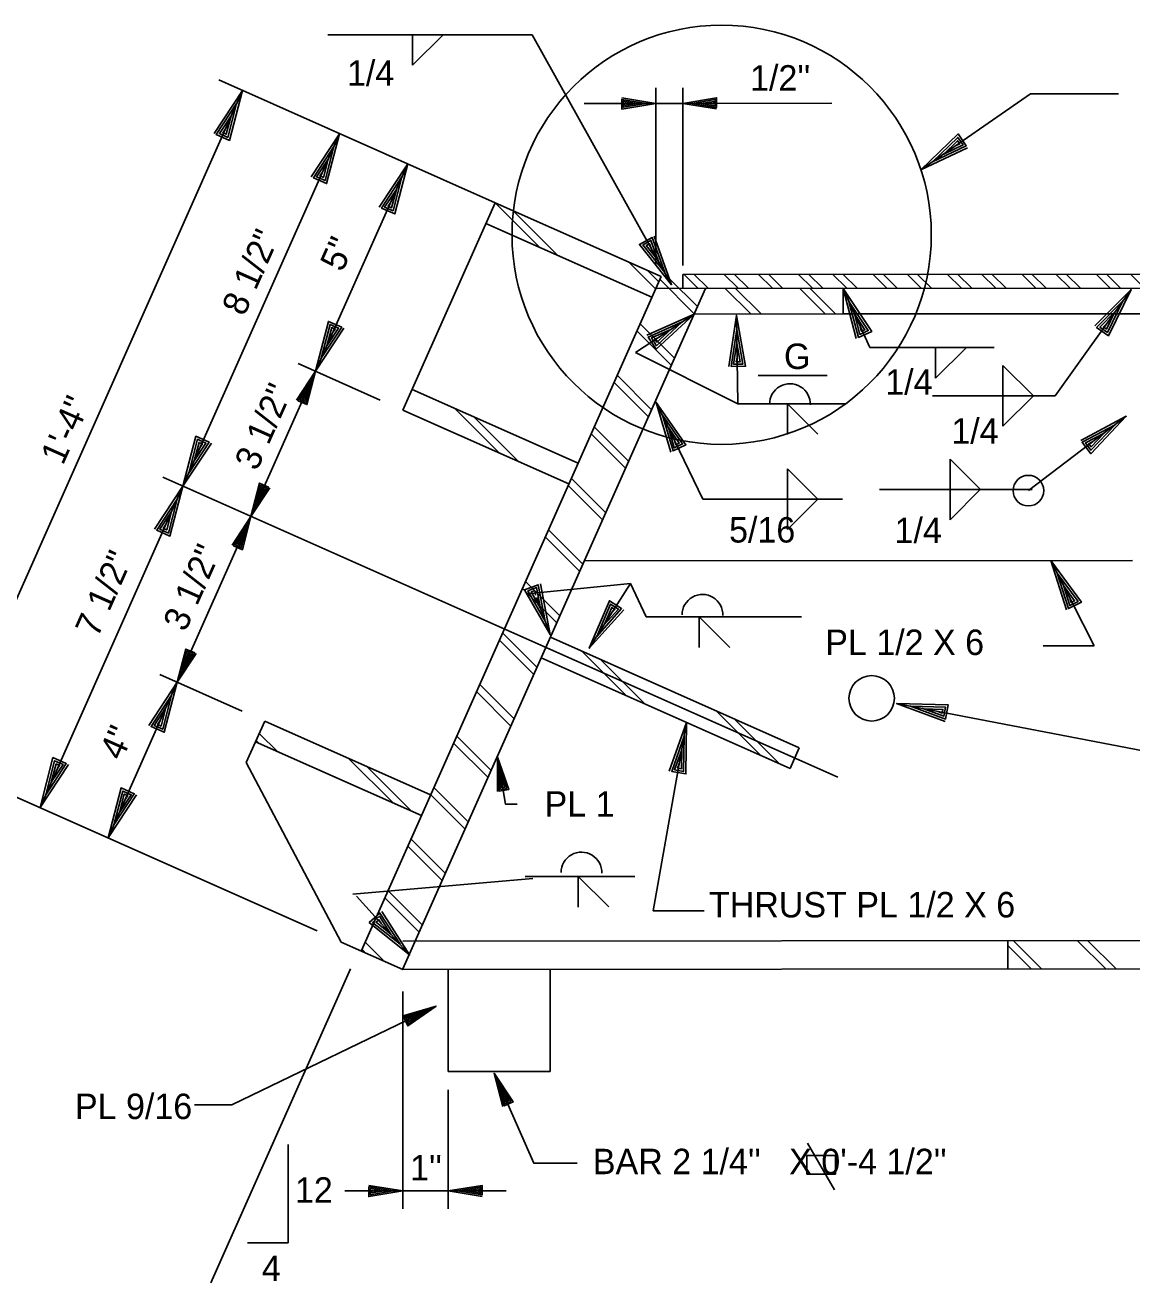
# Model space of a CAD drawing. Extents: x 0.1 to 13.5, y 0.1 to 9.5.
# Drawn here: x 1.182 to 3.214, y 3.086 to 5.396 of the extents above; entities that cross this region are included whole.
import ezdxf

# ---------------------------------------------------------------- set-up
doc = ezdxf.new("R2010")
doc.units = 0
for name, color, linetype in [('Level 1', 7, 'Continuous'), ('Level 25', 7, 'Continuous'), ('Level 3', 7, 'Continuous'), ('Level 44', 7, 'Continuous'), ('Level 50', 7, 'Continuous')]:
    doc.layers.add(name, color=color, linetype=linetype)

msp = doc.modelspace()

# ---------------------------------------------------------------- linework, layer by layer
at = {"layer": 'Level 1'}
for p, q in [((3.0509, 4.2563), (3.1448, 4.2563)), ((2.335, 3.7695), (2.4289, 3.7695)), ((1.7687, 3.255), (1.8752, 3.255)), ((1.8752, 3.255), (1.9586, 3.255)), ((1.9586, 3.255), (2.0649, 3.255)), ((1.5901, 3.1597), (1.6649, 3.1597))]:
    msp.add_line(p, q, dxfattribs=at)
at = {"layer": 'Level 25'}
for p, q in [((2.113, 5.3781), (1.7379, 5.3781)), ((1.8933, 5.3787), (1.8933, 5.3224)), ((1.8933, 5.3224), (1.9492, 5.3783)), ((2.113, 5.3781), (2.3689, 4.9191)), ((1.5374, 5.2951), (2.0449, 5.0696)), ((1.0308, 4.0382), (1.5809, 5.2758)), ((2.3397, 4.9544), (2.3397, 5.281)), ((2.3893, 4.9544), (2.3893, 5.281)), ((2.3397, 5.2522), (2.2081, 5.2521)), ((2.3397, 5.2522), (2.3397, 5.2522)), ((2.3893, 5.2522), (2.3397, 5.2522)), ((2.6633, 5.2524), (2.3893, 5.2522)), ((2.3893, 5.2522), (2.3893, 5.2522)), ((1.4716, 4.5493), (1.7593, 5.1965)), ((1.7151, 4.7602), (1.8843, 5.1409)), ((1.8757, 4.6888), (2.0449, 5.0696)), ((2.0449, 5.0696), (2.3495, 4.9342)), ((2.3326, 4.8961), (2.028, 5.0315)), ((1.7995, 3.6966), (2.3495, 4.9342)), ((2.3563, 4.9418), (2.3563, 4.9418)), ((4.3479, 4.9394), (2.3893, 4.9382)), ((2.3893, 4.9119), (2.3893, 4.938)), ((1.8757, 3.6628), (2.4309, 4.9122)), ((4.3479, 4.9133), (2.3397, 4.9121)), ((2.3689, 4.9191), (2.3689, 4.9191)), ((2.6838, 4.8654), (2.6838, 4.9123)), ((2.7327, 4.8036), (2.6838, 4.9123)), ((2.6838, 4.9123), (2.6838, 4.9123)), ((3.0732, 4.7152), (3.2126, 4.9106)), ((3.2126, 4.9106), (3.2126, 4.9106)), ((2.6944, 4.8886), (2.6944, 4.8886)), ((3.1975, 4.8894), (3.1975, 4.8894)), ((2.3027, 4.7944), (2.4101, 4.8653)), ((2.3884, 4.8509), (2.3884, 4.8509)), ((2.6838, 4.8654), (2.4101, 4.8653)), ((2.4101, 4.8653), (2.4101, 4.8653)), ((2.4903, 4.7006), (2.488, 4.8628)), ((2.488, 4.8628), (2.488, 4.8628)), ((4.3479, 4.8664), (2.6838, 4.8654)), ((2.4884, 4.8368), (2.4884, 4.8368)), ((2.4903, 4.7006), (2.3027, 4.7944)), ((2.7327, 4.8036), (2.9611, 4.8036)), ((2.8537, 4.8036), (2.8537, 4.7473)), ((2.8537, 4.7473), (2.9096, 4.8032)), ((1.5966, 4.4937), (1.7151, 4.7602)), ((1.6833, 4.7743), (1.8339, 4.7074)), ((1.7151, 4.7602), (1.7151, 4.7602)), ((2.9773, 4.7708), (3.0332, 4.715)), ((2.9773, 4.7146), (2.9773, 4.7708)), ((2.6546, 4.7524), (2.5277, 4.7524)), ((2.1972, 4.5915), (1.8926, 4.7269)), ((3.0732, 4.7152), (2.8478, 4.7152)), ((3.0732, 4.7152), (2.9269, 4.7152)), ((2.9773, 4.7158), (2.9773, 4.6595)), ((2.9773, 4.6595), (3.0332, 4.7154)), ((2.1803, 4.5534), (1.8757, 4.6888)), ((1.8757, 4.6888), (1.8757, 4.6888)), ((2.4263, 4.5254), (2.3408, 4.7029)), ((2.3408, 4.7029), (2.3408, 4.7029)), ((2.4903, 4.7006), (2.6888, 4.7006)), ((2.5818, 4.7006), (2.5818, 4.6443)), ((2.5818, 4.7006), (2.6377, 4.6446)), ((2.3521, 4.6794), (2.3521, 4.6794)), ((3.024, 4.541), (3.2038, 4.6777)), ((3.2038, 4.6777), (3.2038, 4.6777)), ((3.1831, 4.6619), (3.1831, 4.6619)), ((2.8802, 4.5991), (2.9361, 4.5432)), ((2.8802, 4.5428), (2.8802, 4.5991)), ((2.5817, 4.5811), (2.6376, 4.5252)), ((2.5817, 4.5248), (2.5817, 4.5811)), ((2.6744, 4.0147), (1.4348, 4.5656)), ((1.2092, 3.9589), (1.4716, 4.5492)), ((3.0312, 4.5434), (2.7507, 4.5434)), ((3.0312, 4.5434), (2.8298, 4.5434)), ((2.8802, 4.544), (2.8802, 4.4877)), ((2.8802, 4.4877), (2.9361, 4.5436)), ((2.6824, 4.5254), (2.4263, 4.5254)), ((2.6824, 4.5254), (2.4263, 4.5254)), ((2.5817, 4.526), (2.5817, 4.4698)), ((2.5817, 4.4698), (2.6376, 4.5256)), ((1.4613, 4.1891), (1.5966, 4.4937)), ((1.5966, 4.4937), (1.5966, 4.4937)), ((3.2154, 4.4126), (2.2087, 4.412)), ((2.2932, 4.3702), (2.1098, 4.3522)), ((2.2932, 4.3702), (2.2177, 4.2515)), ((2.322, 4.309), (2.2932, 4.3702)), ((2.1206, 4.345), (2.1458, 4.2767)), ((2.1368, 4.3011), (2.1368, 4.3011)), ((2.322, 4.309), (2.6072, 4.309)), ((2.4196, 4.309), (2.4196, 4.2528)), ((2.4196, 4.309), (2.4756, 4.2531)), ((2.1458, 4.2767), (2.1458, 4.2767)), ((2.2317, 4.2734), (2.2317, 4.2734)), ((2.6034, 4.069), (2.1465, 4.2721)), ((2.2177, 4.2515), (2.2177, 4.2515)), ((2.5865, 4.031), (2.1296, 4.234)), ((1.3343, 3.9034), (1.4613, 4.1891)), ((1.4295, 4.2032), (1.5801, 4.1363)), ((1.588, 4.0415), (1.6219, 4.1177)), ((1.9265, 3.9823), (1.6219, 4.1177)), ((1.6219, 4.1177), (1.6219, 4.1177)), ((0.955, 4.0719), (1.7181, 3.7328)), ((1.9096, 3.9442), (1.6049, 4.0796)), ((1.6049, 4.0796), (1.6049, 4.0796)), ((2.5865, 4.031), (2.6034, 4.069)), ((2.1142, 3.8288), (1.7834, 3.8)), ((2.0998, 3.8324), (2.3012, 3.8324)), ((2.1974, 3.8324), (2.1974, 3.7762)), ((2.1974, 3.8324), (2.2534, 3.7765)), ((1.7906, 3.7964), (1.8877, 3.6885)), ((1.8752, 3.6618), (1.7622, 3.7121)), ((1.8703, 3.7079), (1.8703, 3.7079)), ((4.3486, 3.7154), (1.8752, 3.7139)), ((2.9862, 3.6625), (2.9862, 3.7146)), ((1.8877, 3.6885), (1.8877, 3.6885)), ((1.523, 3.0863), (1.7793, 3.663)), ((4.3486, 3.6633), (1.8752, 3.6618)), ((1.9586, 3.4744), (1.9586, 3.6617)), ((2.1461, 3.4744), (2.1461, 3.6617)), ((1.8752, 3.2219), (1.8752, 3.6213)), ((2.1461, 3.4745), (1.9586, 3.4744)), ((1.9586, 3.2219), (1.9586, 3.4404)), ((1.6649, 3.1597), (1.6649, 3.3406)), ((2.6681, 3.2568), (2.6183, 3.3429)), ((2.6698, 3.3203), (2.6175, 3.3203)), ((2.6175, 3.2861), (2.6175, 3.3203)), ((2.6698, 3.2861), (2.6698, 3.3203)), ((2.6698, 3.2861), (2.6175, 3.2861))]:
    msp.add_line(p, q, dxfattribs=at)
for points in [[(2.3369, 5.0083), (2.3689, 4.9191), (2.3098, 4.9932), (2.333, 5.0061), (2.3563, 4.9418), (2.3162, 4.9921), (2.331, 5.0004), (2.3441, 4.9636), (2.3225, 4.9911), (2.3286, 4.9945), (2.3314, 4.9863)], [(2.708, 4.8207), (2.6838, 4.9123), (2.7363, 4.8334), (2.7121, 4.8225), (2.6944, 4.8886), (2.7301, 4.835), (2.7146, 4.828), (2.7047, 4.8658), (2.7239, 4.8366), (2.7175, 4.8337), (2.7154, 4.8421)], [(3.1457, 4.8435), (3.2126, 4.9106), (3.1709, 4.8255), (3.1493, 4.8409), (3.1975, 4.8894), (3.1692, 4.8316), (3.1553, 4.8415), (3.183, 4.8691), (3.1674, 4.8378), (3.1617, 4.8418), (3.1679, 4.8479)], [(2.3235, 4.8267), (2.4101, 4.8653), (2.3406, 4.8008), (2.326, 4.8229), (2.3884, 4.8509), (2.3412, 4.8072), (2.3318, 4.8214), (2.3675, 4.8372), (2.3418, 4.8136), (2.3379, 4.8194), (2.3458, 4.8228)], [(2.4738, 4.7691), (2.488, 4.8628), (2.5048, 4.7695), (2.4783, 4.7691), (2.4884, 4.8368), (2.4998, 4.7734), (2.4828, 4.7732), (2.4887, 4.8118), (2.4947, 4.7774), (2.4877, 4.7773), (2.4891, 4.7858)], [(2.3674, 4.6119), (2.3408, 4.7029), (2.3953, 4.6254), (2.3715, 4.6139), (2.3521, 4.6794), (2.3891, 4.6268), (2.3738, 4.6194), (2.3629, 4.6569), (2.3828, 4.6282), (2.3765, 4.6252), (2.3742, 4.6335)], [(3.12, 4.6334), (3.2038, 4.6777), (3.1388, 4.6088), (3.1227, 4.6299), (3.1831, 4.6619), (3.1389, 4.6152), (3.1286, 4.6287), (3.1632, 4.6468), (3.1391, 4.6216), (3.1348, 4.6271), (3.1425, 4.6311)], [(2.128, 4.3698), (2.1458, 4.2767), (2.0989, 4.359), (2.1238, 4.3682), (2.1368, 4.3011), (2.105, 4.357), (2.121, 4.3629), (2.1282, 4.3245), (2.1111, 4.355), (2.1177, 4.3574), (2.1192, 4.3489)], [(2.281, 4.3221), (2.2177, 4.2515), (2.2548, 4.3387), (2.2772, 4.3245), (2.2317, 4.2734), (2.2569, 4.3326), (2.2713, 4.3235), (2.2451, 4.2945), (2.259, 4.3266), (2.2649, 4.3228), (2.2591, 4.3164)], [(1.8367, 3.7684), (1.8877, 3.6885), (1.8136, 3.7477), (1.8333, 3.7654), (1.8703, 3.7079), (1.82, 3.7481), (1.8326, 3.7594), (1.8536, 3.7265), (1.8264, 3.7484), (1.8316, 3.7531), (1.8362, 3.7458)]]:
    msp.add_lwpolyline(points, dxfattribs=at)
for centre, radius in [((2.4608, 5.0109), 0.3849), ((3.024, 4.541), 0.0281), ((2.7363, 4.1597), 0.0417)]:
    msp.add_circle(centre, radius, dxfattribs=at)
for centre in [(2.5862, 4.6998), (2.4256, 4.3129), (2.2034, 3.8396)]:
    msp.add_arc(centre, 0.0375, 358.4208, 180, dxfattribs=at)
at = {"layer": 'Level 3'}
for p, q in [((2.0495, 4.0518), (2.0495, 4.0518)), ((2.0523, 4.0347), (2.0523, 4.0347)), ((1.9209, 3.5869), (1.9209, 3.5869)), ((1.9365, 3.5944), (1.9365, 3.5944)), ((2.0431, 3.4713), (2.0431, 3.4713)), ((2.0501, 3.4554), (2.0501, 3.4554))]:
    msp.add_line(p, q, dxfattribs=at)
for points in [[(2.0854, 3.9655), (2.0639, 3.9655), (2.0495, 4.0518)], [(2.0495, 3.9886), (2.0495, 4.0518), (2.0699, 3.992), (2.0525, 3.9891), (2.0523, 4.0347), (2.0662, 3.9941), (2.055, 3.9923), (2.0551, 4.0183), (2.0625, 3.9962), (2.0579, 3.9954), (2.0579, 4.0012)], [(1.493, 3.4134), (1.5614, 3.4134), (1.9365, 3.5944)], [(1.8759, 3.5766), (1.9365, 3.5944), (1.8848, 3.558), (1.8772, 3.5739), (1.9209, 3.5869), (1.8858, 3.5622), (1.8809, 3.5724), (1.9059, 3.5796), (1.8868, 3.5663), (1.8847, 3.5705), (1.8903, 3.5721)], [(2.1954, 3.3058), (2.1159, 3.3058), (2.0431, 3.4713)], [(2.0588, 3.4101), (2.0431, 3.4713), (2.0777, 3.4184), (2.0615, 3.4113), (2.0501, 3.4554), (2.0736, 3.4195), (2.0632, 3.4149), (2.0568, 3.4402), (2.0694, 3.4206), (2.0652, 3.4187), (2.0638, 3.4243)]]:
    msp.add_lwpolyline(points, dxfattribs=at)
at = {"layer": 'Level 44'}
for p, q in [((3.0279, 5.2697), (2.8268, 5.1301)), ((3.0279, 5.2697), (3.1892, 5.2697)), ((2.1269, 4.9875), (2.0449, 5.0695)), ((2.1609, 4.9724), (2.0788, 5.0545)), ((2.3395, 4.9116), (2.2909, 4.9602)), ((2.3453, 4.9247), (2.3249, 4.9451)), ((2.4104, 4.866), (2.3473, 4.9291)), ((2.4162, 4.879), (2.3653, 4.9299)), ((2.4166, 4.9133), (2.3917, 4.9382)), ((2.4354, 4.9133), (2.4106, 4.9382)), ((2.4903, 4.9133), (2.4654, 4.9382)), ((2.5092, 4.9133), (2.4843, 4.9382)), ((2.5533, 4.9133), (2.5284, 4.9382)), ((2.5722, 4.9133), (2.5473, 4.9382)), ((2.627, 4.9133), (2.6021, 4.9382)), ((2.6459, 4.9133), (2.621, 4.9382)), ((2.69, 4.9133), (2.6651, 4.9382)), ((2.7089, 4.9133), (2.684, 4.9382)), ((2.7637, 4.9133), (2.7388, 4.9382)), ((2.7826, 4.9133), (2.7577, 4.9382)), ((2.8267, 4.9133), (2.8018, 4.9382)), ((2.8456, 4.9133), (2.8207, 4.9382)), ((2.9004, 4.9133), (2.8755, 4.9382)), ((2.9193, 4.9133), (2.8944, 4.9382)), ((2.9634, 4.9133), (2.9386, 4.9382)), ((2.9823, 4.9133), (2.9574, 4.9382)), ((3.0371, 4.9133), (3.0123, 4.9382)), ((3.056, 4.9133), (3.0311, 4.9382)), ((3.1001, 4.9133), (3.0753, 4.9382)), ((3.119, 4.9133), (3.0941, 4.9382)), ((3.1738, 4.9133), (3.149, 4.9382)), ((3.1927, 4.9133), (3.1678, 4.9382)), ((3.2368, 4.9133), (3.212, 4.9382)), ((2.5143, 4.8654), (2.4675, 4.9122)), ((2.5331, 4.8654), (2.4864, 4.9122)), ((2.651, 4.8654), (2.6042, 4.9122)), ((2.6698, 4.8654), (2.6231, 4.9122)), ((2.3684, 4.7713), (2.3052, 4.8344)), ((2.3742, 4.7844), (2.311, 4.8475)), ((2.3263, 4.6767), (2.2632, 4.7398)), ((2.3321, 4.6897), (2.269, 4.7529)), ((2.0531, 4.61), (1.9711, 4.692)), ((2.0871, 4.5949), (2.005, 4.6769)), ((2.2842, 4.582), (2.2211, 4.6452)), ((2.29, 4.5951), (2.2269, 4.6582)), ((2.2422, 4.4874), (2.179, 4.5505)), ((2.248, 4.5004), (2.1848, 4.5636)), ((2.2059, 4.4058), (2.1428, 4.4689)), ((2.2001, 4.3927), (2.137, 4.4559)), ((3.1448, 4.2563), (3.0651, 4.4125)), ((2.1638, 4.3112), (2.1007, 4.3743)), ((2.158, 4.2981), (2.0949, 4.3612)), ((2.1218, 4.2165), (2.0586, 4.2796)), ((2.116, 4.2035), (2.0528, 4.2666)), ((2.2861, 4.1644), (2.204, 4.2465)), ((2.32, 4.1494), (2.2379, 4.2315)), ((2.0797, 4.1219), (2.0166, 4.185)), ((2.0739, 4.1088), (2.0108, 4.1719)), ((2.5322, 4.0551), (2.4501, 4.1372)), ((3.5935, 3.9938), (2.782, 4.1501)), ((2.335, 3.7695), (2.3963, 4.1155)), ((2.5661, 4.04), (2.484, 4.1221)), ((1.6459, 4.0614), (1.6119, 4.0953)), ((2.0376, 4.0272), (1.9745, 4.0904)), ((1.6119, 4.0765), (1.6061, 4.0823)), ((2.0318, 4.0142), (1.9687, 4.0773)), ((1.858, 3.9671), (1.7759, 4.0492)), ((1.7622, 3.7121), (1.588, 4.0415)), ((1.8919, 3.952), (1.8099, 4.0341)), ((1.9956, 3.9326), (1.9324, 3.9957)), ((1.9898, 3.9195), (1.9266, 3.9827)), ((1.9477, 3.8249), (1.8846, 3.888)), ((1.9535, 3.8379), (1.8904, 3.9011)), ((1.9056, 3.7302), (1.8425, 3.7934)), ((1.9114, 3.7433), (1.8483, 3.8064)), ((1.805, 3.6941), (1.8005, 3.6987)), ((1.839, 3.6791), (1.8063, 3.7118)), ((3.0293, 3.6628), (2.9862, 3.7059)), ((3.0482, 3.6628), (2.9964, 3.7146)), ((3.166, 3.6628), (3.1143, 3.7146)), ((3.1849, 3.6628), (3.1331, 3.7146))]:
    msp.add_line(p, q, dxfattribs=at)
at = {"layer": 'Level 50'}
for p, q in [((1.5809, 5.2758), (1.5809, 5.2758)), ((1.5703, 5.252), (1.5703, 5.252)), ((2.3224, 5.2522), (2.3224, 5.2522)), ((2.3397, 5.2522), (2.3397, 5.2522)), ((2.3893, 5.2522), (2.3893, 5.2522)), ((2.4066, 5.2522), (2.4066, 5.2522)), ((1.7593, 5.1965), (1.7593, 5.1965)), ((1.7487, 5.1727), (1.7487, 5.1727)), ((1.8843, 5.1409), (1.8843, 5.1409)), ((2.8268, 5.1301), (2.8268, 5.1301)), ((2.8482, 5.1449), (2.8482, 5.1449)), ((1.8738, 5.1172), (1.8738, 5.1172)), ((1.7257, 4.784), (1.7257, 4.784)), ((1.7151, 4.7602), (1.7151, 4.7602)), ((1.7151, 4.7602), (1.7151, 4.7602)), ((1.7081, 4.7444), (1.7081, 4.7444)), ((1.4822, 4.573), (1.4822, 4.573)), ((1.4716, 4.5493), (1.4716, 4.5493)), ((1.4716, 4.5492), (1.4716, 4.5492)), ((1.4611, 4.5255), (1.4611, 4.5255)), ((1.6037, 4.5095), (1.6037, 4.5095)), ((1.5966, 4.4937), (1.5966, 4.4937)), ((1.5966, 4.4937), (1.5966, 4.4937)), ((1.5896, 4.4778), (1.5896, 4.4778)), ((3.0651, 4.4125), (3.0651, 4.4125)), ((3.0769, 4.3894), (3.0769, 4.3894)), ((1.4683, 4.2049), (1.4683, 4.2049)), ((1.4613, 4.1891), (1.4613, 4.1891)), ((1.4613, 4.1891), (1.4613, 4.1891)), ((1.4507, 4.1653), (1.4507, 4.1653)), ((2.782, 4.1501), (2.782, 4.1501)), ((2.8076, 4.1451), (2.8076, 4.1451)), ((2.3963, 4.1155), (2.3963, 4.1155)), ((2.3917, 4.0899), (2.3917, 4.0899)), ((1.2198, 3.9827), (1.2198, 3.9827)), ((1.2092, 3.9589), (1.2092, 3.9589)), ((1.3448, 3.9271), (1.3448, 3.9271)), ((1.3343, 3.9034), (1.3343, 3.9034)), ((1.8579, 3.255), (1.8579, 3.255)), ((1.8752, 3.255), (1.8752, 3.255)), ((1.9586, 3.255), (1.9586, 3.255)), ((1.9759, 3.255), (1.9759, 3.255))]:
    msp.add_line(p, q, dxfattribs=at)
for points in [[(1.5288, 5.1966), (1.5809, 5.2758), (1.5571, 5.184), (1.5329, 5.1948), (1.5703, 5.252), (1.5541, 5.1897), (1.5386, 5.1966), (1.5602, 5.2292), (1.5512, 5.1954), (1.5448, 5.1983), (1.5496, 5.2054)], [(2.2774, 5.2625), (2.3397, 5.2522), (2.2774, 5.2418), (2.2774, 5.2595), (2.3224, 5.2522), (2.2801, 5.2451), (2.2801, 5.2565), (2.3057, 5.2522), (2.2827, 5.2485), (2.2827, 5.2531), (2.2884, 5.2521)], [(2.4516, 5.2419), (2.3893, 5.2522), (2.4516, 5.2626), (2.4516, 5.2449), (2.4066, 5.2522), (2.4489, 5.2592), (2.4489, 5.2479), (2.4233, 5.2522), (2.4463, 5.2559), (2.4463, 5.2512), (2.4406, 5.2522)], [(1.7072, 5.1173), (1.7593, 5.1965), (1.7355, 5.1048), (1.7113, 5.1155), (1.7487, 5.1727), (1.7325, 5.1104), (1.717, 5.1173), (1.7386, 5.1499), (1.7296, 5.1161), (1.7232, 5.119), (1.728, 5.1261)], [(2.9125, 5.1707), (2.8268, 5.1301), (2.8948, 5.1961), (2.9099, 5.1744), (2.8482, 5.1449), (2.8944, 5.1898), (2.9041, 5.1758), (2.8687, 5.1592), (2.8939, 5.1834), (2.8979, 5.1776), (2.8901, 5.174)], [(1.8322, 5.0618), (1.8843, 5.1409), (1.8605, 5.0492), (1.8363, 5.06), (1.8738, 5.1172), (1.8576, 5.0549), (1.842, 5.0618), (1.8636, 5.0943), (1.8546, 5.0606), (1.8482, 5.0634), (1.8531, 5.0706)], [(1.7672, 4.8393), (1.7151, 4.7602), (1.7389, 4.8519), (1.7631, 4.8412), (1.7257, 4.784), (1.7419, 4.8463), (1.7574, 4.8393), (1.7358, 4.8068), (1.7448, 4.8406), (1.7512, 4.8377), (1.7464, 4.8306)], [(1.6803, 4.7074), (1.7151, 4.7602), (1.6992, 4.699), (1.6831, 4.7062), (1.7081, 4.7444), (1.6973, 4.7028), (1.6869, 4.7074), (1.7013, 4.7291), (1.6953, 4.7066), (1.691, 4.7085), (1.6943, 4.7133)], [(1.5238, 4.6284), (1.4716, 4.5493), (1.4954, 4.641), (1.5196, 4.6302), (1.4822, 4.573), (1.4984, 4.6353), (1.5139, 4.6284), (1.4923, 4.5959), (1.5013, 4.6296), (1.5077, 4.6268), (1.5029, 4.6196)], [(1.6314, 4.5464), (1.5966, 4.4937), (1.6125, 4.5548), (1.6287, 4.5477), (1.6037, 4.5095), (1.6145, 4.551), (1.6248, 4.5464), (1.6105, 4.5248), (1.6164, 4.5473), (1.6207, 4.5454), (1.6175, 4.5406)], [(1.4195, 4.4701), (1.4716, 4.5492), (1.4478, 4.4575), (1.4236, 4.4683), (1.4611, 4.5255), (1.4449, 4.4632), (1.4293, 4.4701), (1.4509, 4.5026), (1.4419, 4.4689), (1.4355, 4.4717), (1.4403, 4.4789)], [(1.5619, 4.4409), (1.5966, 4.4937), (1.5808, 4.4325), (1.5646, 4.4397), (1.5896, 4.4778), (1.5788, 4.4363), (1.5684, 4.4409), (1.5828, 4.4626), (1.5768, 4.4401), (1.5726, 4.442), (1.5758, 4.4468)], [(3.0938, 4.3222), (3.0651, 4.4125), (3.1214, 4.3363), (3.0978, 4.3243), (3.0769, 4.3894), (3.1151, 4.3376), (3.1, 4.3299), (3.0883, 4.3671), (3.1089, 4.3389), (3.1026, 4.3357), (3.1001, 4.344)], [(1.496, 4.2418), (1.4613, 4.1891), (1.4771, 4.2502), (1.4933, 4.243), (1.4683, 4.2049), (1.4791, 4.2464), (1.4894, 4.2418), (1.4751, 4.2201), (1.4811, 4.2426), (1.4853, 4.2407), (1.4821, 4.236)], [(1.4091, 4.1099), (1.4613, 4.1891), (1.4374, 4.0973), (1.4132, 4.1081), (1.4507, 4.1653), (1.4345, 4.103), (1.419, 4.1099), (1.4405, 4.1425), (1.4316, 4.1087), (1.4252, 4.1115), (1.43, 4.1187)], [(2.8709, 4.1171), (2.782, 4.1501), (2.8768, 4.1476), (2.8718, 4.1216), (2.8076, 4.1451), (2.8719, 4.1434), (2.8687, 4.1267), (2.8321, 4.1404), (2.867, 4.1393), (2.8657, 4.1324), (2.8577, 4.1355)], [(2.3647, 4.0261), (2.3963, 4.1155), (2.3952, 4.0207), (2.3691, 4.0253), (2.3917, 4.0899), (2.391, 4.0255), (2.3743, 4.0285), (2.3874, 4.0653), (2.3868, 4.0303), (2.3799, 4.0316), (2.3828, 4.0397)], [(1.2614, 4.0381), (1.2092, 3.9589), (1.233, 4.0507), (1.2573, 4.0399), (1.2198, 3.9827), (1.236, 4.045), (1.2515, 4.0381), (1.2299, 4.0055), (1.2389, 4.0393), (1.2453, 4.0365), (1.2405, 4.0293)], [(1.3864, 3.9825), (1.3343, 3.9034), (1.3581, 3.9951), (1.3823, 3.9843), (1.3448, 3.9271), (1.361, 3.9894), (1.3766, 3.9825), (1.355, 3.95), (1.364, 3.9837), (1.3704, 3.9809), (1.3655, 3.9737)], [(1.8129, 3.2653), (1.8752, 3.255), (1.8129, 3.2447), (1.8129, 3.2623), (1.8579, 3.255), (1.8156, 3.248), (1.8156, 3.2593), (1.8412, 3.255), (1.8182, 3.2513), (1.8182, 3.256), (1.8239, 3.255)], [(2.0209, 3.2447), (1.9586, 3.255), (2.0209, 3.2653), (2.0209, 3.2477), (1.9759, 3.255), (2.0182, 3.262), (2.0182, 3.2507), (1.9926, 3.255), (2.0156, 3.2587), (2.0156, 3.254), (2.0099, 3.255)]]:
    msp.add_lwpolyline(points, dxfattribs=at)

# ---------------------------------------------------------------- texts
at = {"layer": 'Level 1'}
for s, p in [('1/4', (1.7728, 5.2844)), ('1/4', (2.7612, 4.7173)), ('1/4', (2.8825, 4.6273)), ('1/4', (2.7783, 4.4448)), ('PL 9/16', (1.2734, 3.387))]:
    msp.add_text(s, height=0.0467, dxfattribs=at).set_placement(p)
at = {"layer": 'Level 25'}
for s, rotation, p in [("1/2''", 0.0347, (2.513, 5.2756)), ('8 1/2"', 66.0359, (1.584, 4.8595)), ('5"', 66.0359, (1.7644, 4.9408)), ("3 1/2''", 66.0367, (1.6075, 4.5754)), ("1'-4''", 66.0358, (1.2513, 4.5861)), ("3 1/2''", 66.0364, (1.4762, 4.28)), ('7 1/2"', 66.0359, (1.3148, 4.2694)), ('4"', 66.0359, (1.3595, 4.0434))]:
    msp.add_text(s, height=0.0467, rotation=rotation, dxfattribs=at).set_placement(p)
for s, height, p in [('G', 0.0467, (2.5752, 4.7644)), ('5/16', 0.0467, (2.4744, 4.4457)), ('PL 1/2 X 6', 0.0467, (2.651, 4.2392)), ('PL 1', 0.0467, (2.1356, 3.9424)), ('THRUST PL 1/2 X 6', 0.046698, (2.4375, 3.7573)), ("BAR 2 1/4''   X 0'-4 1/2''", 0.046698, (2.2243, 3.2858)), ("1''", 0.0467, (1.8886, 3.2743)), ('12', 0.0467, (1.6773, 3.2334)), ('4', 0.0467, (1.6166, 3.0897))]:
    msp.add_text(s, height=height, dxfattribs=at).set_placement(p)

doc.saveas('drawing.dxf')
